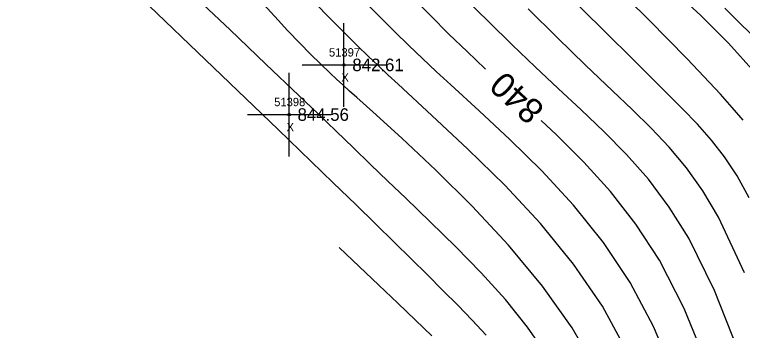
# Model space of a CAD drawing. Extents: x 1378535 to 1380697, y 997729 to 1000024.
# Drawn here: x 1380135 to 1380222, y 998356.1 to 998393.8 of the extents above; entities that cross this region are included whole.
import ezdxf

# ---------------------------------------------------------------- set-up
doc = ezdxf.new("R2010")
doc.units = 0
for name, color, linetype in [('RD_DTM_Major1', 7, 'Continuous'), ('RD_DTM_Major1_Lbl', 7, 'Continuous'), ('RD_DTM_Minor1', 7, 'Continuous'), ('RD_EX_Misc', 7, 'Continuous'), ('RD_EX_Misc_txCode', 7, 'Continuous'), ('RD_EX_Road', 7, 'Continuous'), ('RD_EX_TX_Misc_ELEV', 7, 'Continuous'), ('RD_SMD_Locator', 7, 'Continuous')]:
    doc.layers.add(name, color=color, linetype=linetype)

msp = doc.modelspace()

# ---------------------------------------------------------------- linework, layer by layer
at = {"layer": 'RD_DTM_Major1'}
for points in [[(1380191.325, 998387.302), (1380191.279, 998387.345), (1380189.11, 998389.409), (1380186.944, 998391.516), (1380184.715, 998393.728), (1380182.355, 998396.106), (1380179.798, 998398.711), (1380175.089, 998403.547), (1380169.915, 998408.9), (1380164.523, 998414.506), (1380159.159, 998420.106), (1380154.072, 998425.439), (1380149.508, 998430.243), (1380147.248, 998432.632), (1380145.21, 998434.797), (1380143.373, 998436.761), (1380141.714, 998438.552), (1380140.211, 998440.195), (1380138.842, 998441.715), (1380137.882, 998442.793), (1380136.962, 998443.808), (1380136.059, 998444.751), (1380135.148, 998445.616), (1380134.206, 998446.393)], [(1380191.367, 998355.493), (1380189.714, 998357.294), (1380187.989, 998359.085), (1380186.225, 998360.867), (1380184.359, 998362.734), (1380182.435, 998364.643), (1380180.401, 998366.647), (1380178.205, 998368.798), (1380175.795, 998371.145), (1380173.119, 998373.741), (1380166.548, 998380.086), (1380158.816, 998387.524), (1380150.156, 998395.836), (1380140.798, 998404.804), (1380136.475, 998408.944)], [(1380249.44, 998318.497), (1380249.032, 998319.786), (1380245.537, 998331.5), (1380241.796, 998344.021), (1380237.915, 998356.374), (1380234.001, 998367.587), (1380230.161, 998376.689), (1380229.538, 998377.928), (1380228.915, 998379.094), (1380228.286, 998380.199), (1380227.645, 998381.255), (1380226.988, 998382.274), (1380226.309, 998383.267), (1380223.479, 998386.935), (1380220.351, 998390.42), (1380217.031, 998393.739), (1380213.624, 998396.909), (1380210.237, 998399.948), (1380206.973, 998402.873), (1380204.544, 998405.109), (1380204.455, 998405.193)], [(1380217.614, 998352.374), (1380215.047, 998358.681), (1380212.083, 998364.469), (1380209.284, 998368.777), (1380206.24, 998372.674), (1380203.046, 998376.215), (1380199.798, 998379.457), (1380197.937, 998381.196)]]:
    msp.add_lwpolyline(points, dxfattribs=at)
at = {"layer": 'RD_DTM_Minor1'}
for points in [[(1380207.694, 998354.479), (1380205.271, 998358.958), (1380201.826, 998364.019), (1380197.87, 998368.85), (1380193.598, 998373.433), (1380189.208, 998377.749), (1380184.896, 998381.779), (1380180.857, 998385.504), (1380179.651, 998386.631), (1380178.468, 998387.751), (1380177.28, 998388.89), (1380176.063, 998390.073), (1380174.789, 998391.328), (1380173.434, 998392.679), (1380167.002, 998399.234), (1380159.502, 998407.031), (1380151.62, 998415.317), (1380144.042, 998423.335), (1380137.455, 998430.332), (1380132.545, 998435.554)], [(1380203.795, 998352.637), (1380201.645, 998356.4), (1380198.132, 998361.382), (1380194.056, 998366.279), (1380189.701, 998370.951), (1380185.355, 998375.257), (1380181.305, 998379.055), (1380177.837, 998382.203), (1380175.919, 998383.933), (1380175.069, 998384.703), (1380174.27, 998385.432), (1380173.504, 998386.137), (1380172.756, 998386.834), (1380171.592, 998387.94), (1380170.389, 998389.12), (1380169.105, 998390.425), (1380167.699, 998391.907), (1380166.131, 998393.616), (1380164.36, 998395.604), (1380159.388, 998401.348), (1380153.432, 998408.196), (1380146.814, 998415.483), (1380139.86, 998422.544), (1380132.894, 998428.713)], [(1380198.623, 998353.153), (1380196.331, 998356.485), (1380193.678, 998359.769), (1380190.781, 998362.977), (1380187.754, 998366.083), (1380184.714, 998369.058), (1380181.776, 998371.875), (1380179.641, 998373.928), (1380177.58, 998375.917), (1380175.54, 998377.891), (1380173.466, 998379.896), (1380171.305, 998381.979), (1380169.001, 998384.186), (1380165.073, 998387.926), (1380160.793, 998392), (1380156.277, 998396.332), (1380151.647, 998400.842), (1380147.02, 998405.453), (1380142.515, 998410.086), (1380138.811, 998414.022), (1380135.276, 998417.795), (1380131.903, 998421.283)], [(1380222.082, 998381.207), (1380220.791, 998382.742), (1380219.378, 998384.323), (1380215.393, 998388.557), (1380210.814, 998393.221), (1380205.921, 998398.082)], [(1380222.816, 998371.935), (1380221.354, 998374.548), (1380219.855, 998376.815), (1380218.292, 998378.841), (1380216.637, 998380.729), (1380214.861, 998382.582), (1380212.936, 998384.505), (1380209.288, 998388.119), (1380205.285, 998392.083), (1380201.087, 998396.246)], [(1380213.699, 998351.075), (1380211.375, 998356.565), (1380208.606, 998361.791), (1380205.395, 998366.589), (1380201.819, 998371.041), (1380198.041, 998375.15), (1380194.228, 998378.917), (1380190.542, 998382.346), (1380187.149, 998385.437), (1380185.429, 998387.026), (1380183.786, 998388.574), (1380182.155, 998390.142), (1380180.47, 998391.793), (1380178.668, 998393.59), (1380176.682, 998395.594)], [(1380221.448, 998353.782), (1380218.679, 998360.856), (1380215.606, 998367.092), (1380213.26, 998370.831), (1380210.764, 998374.144), (1380208.152, 998377.123), (1380205.46, 998379.863), (1380202.724, 998382.457), (1380199.978, 998384.997), (1380197.228, 998387.585), (1380194.475, 998390.236), (1380191.687, 998392.975), (1380188.835, 998395.824)], [(1380222.232, 998362.972), (1380219.141, 998369.621), (1380217.266, 998372.775), (1380215.304, 998375.528), (1380213.249, 998377.989), (1380211.096, 998380.269), (1380208.84, 998382.475), (1380206.474, 998384.719), (1380203.247, 998387.811), (1380199.873, 998391.099), (1380196.398, 998394.533)], [(1380224.679, 998389.873), (1380219.917, 998394.618)], [(1380184.911, 998355.414), (1380182.948, 998357.299), (1380180.814, 998359.336), (1380178.551, 998361.487), (1380176.203, 998363.714), (1380173.812, 998365.978)]]:
    msp.add_lwpolyline(points, dxfattribs=at)
at = {"layer": 'RD_EX_Misc'}
for p, q in [((1380174.398, 998382.827), (1380174.398, 998392.827)), ((1380169.398, 998387.827), (1380179.398, 998387.827)), ((1380167.852, 998376.889), (1380167.852, 998386.889)), ((1380162.852, 998381.889), (1380172.852, 998381.889))]:
    msp.add_line(p, q, dxfattribs=at)
at = {"layer": 'RD_EX_Road'}
for points in [[(1380571.276, 997900.848), (1380553.838, 997963.229), (1380535.074, 998018.791), (1380510.809, 998079.184), (1380486.363, 998133.158), (1380458.393, 998185.941), (1380428.109, 998238.221), (1380392.689, 998291.143), (1380357.52, 998337.623), (1380319.367, 998385.164), (1380279.255, 998428.684), (1380239.596, 998468.129), (1380183.367, 998518.832)], [(1380551.892, 997897.33), (1380534.244, 997958.196), (1380514.831, 998013.467), (1380491.083, 998070.746), (1380467.518, 998124.397), (1380439.882, 998176.529), (1380409.174, 998228.123), (1380375.886, 998278.447), (1380340.748, 998326.222), (1380303.332, 998371.138), (1380263.981, 998413.97), (1380224.662, 998452.644), (1380168.713, 998504.787)]]:
    msp.add_spline(points, degree=3, dxfattribs=at)
at = {"layer": 'RD_SMD_Locator'}
for centre in [(1380174.398, 998387.827), (1380167.852, 998381.889)]:
    msp.add_circle(centre, 0.15, dxfattribs=at)

# ---------------------------------------------------------------- texts
at = {"layer": 'RD_DTM_Major1_Lbl'}
msp.add_text('840', height=3, rotation=137.27887, dxfattribs=at).set_placement((1380198.51, 998382.705))
at = {"layer": 'RD_EX_Misc_txCode'}
for s, p in [('51397', (1380172.603, 998388.827)), ('X', (1380174.083, 998385.827)), ('51398', (1380166.057, 998382.889)), ('X', (1380167.537, 998379.889))]:
    msp.add_text(s, height=1, dxfattribs=at).set_placement(p)
at = {"layer": 'RD_EX_TX_Misc_ELEV'}
for s, p in [('842.61', (1380175.398, 998387.077)), ('844.56', (1380168.852, 998381.139))]:
    msp.add_text(s, height=1.5, dxfattribs=at).set_placement(p)

doc.saveas('drawing.dxf')
